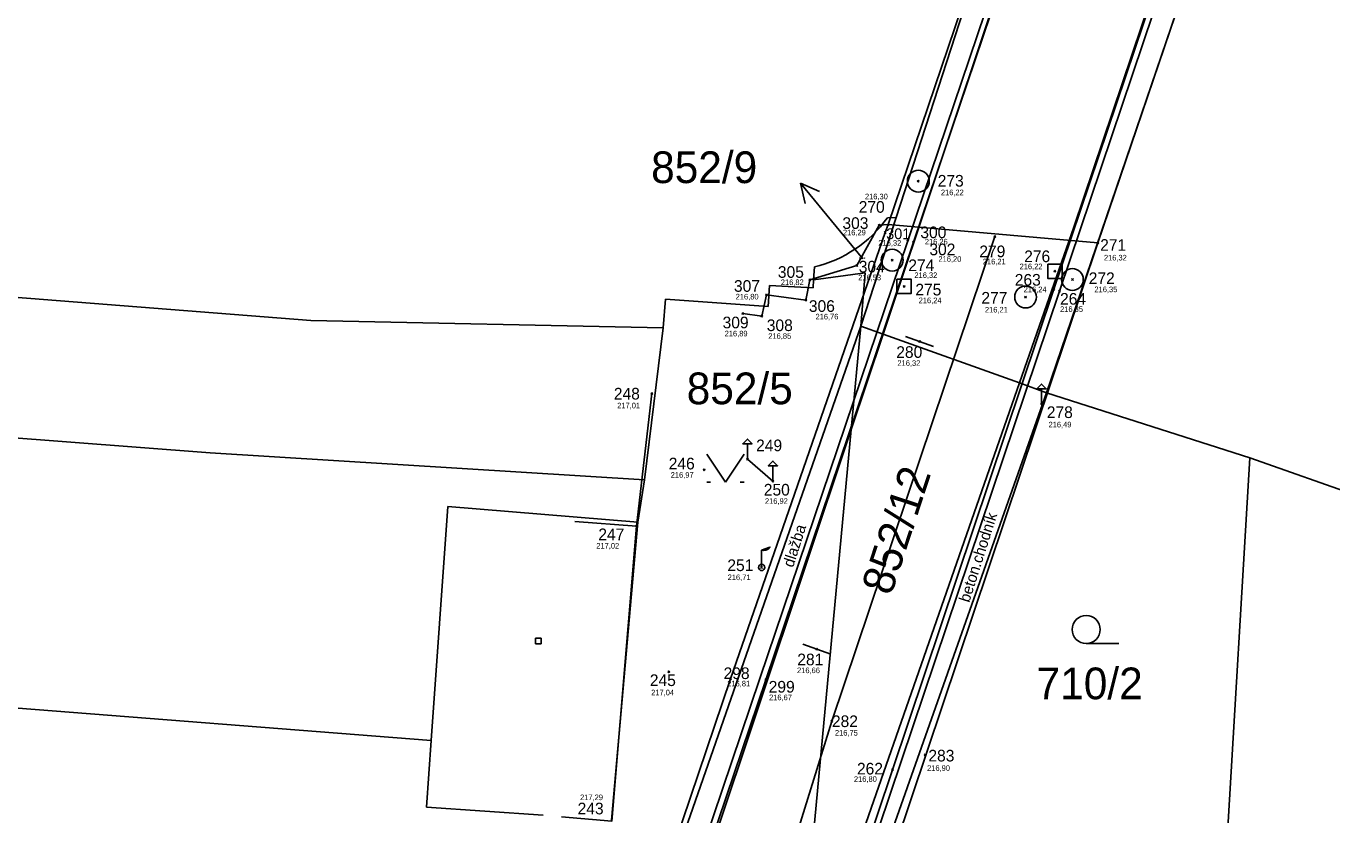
# Model space of a CAD drawing. Extents: x -711879 to -711361, y -1048782 to -1048177.
# Drawn here: x -711669.9 to -711599.9, y -1048480.8 to -1048438.5 of the extents above; entities that cross this region are included whole.
import ezdxf

# ---------------------------------------------------------------- set-up
doc = ezdxf.new("R2010")
doc.units = 0
for name, color, linetype in [('body', 7, 'Continuous'), ('kresba', 7, 'Continuous'), ('Vrstva 1', 7, 'Continuous'), ('Vrstva 13', 7, 'Continuous'), ('Vrstva 14', 7, 'Continuous'), ('Vrstva 16', 7, 'Continuous'), ('Vrstva 2', 7, 'Continuous'), ('Vrstva 20', 7, 'Continuous'), ('Vrstva 23', 7, 'Continuous'), ('Vrstva 25', 7, 'Continuous'), ('Vrstva 41', 7, 'Continuous'), ('Vrstva 46', 7, 'Continuous'), ('výšky', 7, 'Continuous')]:
    doc.layers.add(name, color=color, linetype=linetype)

msp = doc.modelspace()

# ---------------------------------------------------------------- linework, layer by layer
at = {"layer": 'kresba'}
for p, q in [((-711599.74, -1048407.86), (-711614.77, -1048452.56)), ((-711623.82, -1048449.52), (-711623.65, -1048449.1)), ((-711632.11, -1048473.45), (-711623.82, -1048449.52)), ((-711622.61, -1048449.96), (-711630.53, -1048473.44)), ((-711622.3, -1048450.03), (-711630.22, -1048473.51)), ((-711627.89, -1048496.13), (-711612.41, -1048450.08)), ((-711631.45, -1048453.87), (-711631.45, -1048453.87)), ((-711621.97, -1048455.37), (-711622.72, -1048455.1)), ((-711621.22, -1048455.64), (-711621.97, -1048455.37)), ((-711631.2, -1048461.67), (-711629.83, -1048462.85)), ((-711630.44, -1048466.55), (-711630.44, -1048467.48)), ((-711627.48, -1048471.87), (-711628.23, -1048471.6)), ((-711626.73, -1048472.14), (-711627.48, -1048471.87)), ((-711632.11, -1048473.45), (-711637.58, -1048489.62)), ((-711630.53, -1048473.44), (-711636.99, -1048492.57)), ((-711630.22, -1048473.51), (-711636.68, -1048492.64))]:
    msp.add_line(p, q, dxfattribs=at)
for points in [[(-711630.48, -1048500.11), (-711629, -1048495.83), (-711614.47, -1048452.67), (-711599.94, -1048409.51)], [(-711614.09, -1048419.16), (-711613.1, -1048421.84), (-711622.61, -1048449.96)], [(-711613.78, -1048419.23), (-711612.79, -1048421.91), (-711622.3, -1048450.03)], [(-711631.45, -1048453.87), (-711630.43, -1048454.01), (-711630.18, -1048452.87), (-711628.07, -1048453.14), (-711627.85, -1048452.06), (-711625.33, -1048451.29), (-711624.13, -1048449.12), (-711623.65, -1048449.1)], [(-711617.94, -1048449.74), (-711626.67, -1048475.73), (-711634.71, -1048501.65), (-711638.73, -1048513.57), (-711639.471, -1048515.651)], [(-711614.77, -1048452.56), (-711623.43, -1048478.33), (-711629.27, -1048495.74)], [(-711615.43, -1048458.72), (-711615.43, -1048457.9), (-711615.18, -1048457.9), (-711615.43, -1048457.65), (-711615.68, -1048457.9), (-711615.43, -1048457.9)], [(-711631.2, -1048461.67), (-711631.2, -1048460.85), (-711630.95, -1048460.85), (-711631.2, -1048460.6), (-711631.45, -1048460.85), (-711631.2, -1048460.85)], [(-711629.83, -1048462.85), (-711629.83, -1048462.03), (-711629.58, -1048462.03), (-711629.83, -1048461.78), (-711630.08, -1048462.03), (-711629.83, -1048462.03)]]:
    msp.add_lwpolyline(points, dxfattribs=at)
for points in [[(-711614.39, -1048421.71), (-711602.91, -1048422.1), (-711612.41, -1048450.08), (-711623.65, -1048449.1)], [(-711615.105, -1048451.22), (-711614.335, -1048451.22), (-711614.335, -1048451.98), (-711615.105, -1048451.98)], [(-711623.185, -1048452.03), (-711622.415, -1048452.03), (-711622.415, -1048452.79), (-711623.185, -1048452.79)], [(-711630.44, -1048466.55), (-711630.34, -1048466.58), (-711630.21, -1048466.56), (-711630.09, -1048466.5), (-711629.99, -1048466.39)]]:
    msp.add_lwpolyline(points, close=True, dxfattribs=at)
for centre, radius in [((-711622.04, -1048446.77), 0.585), ((-711623.44, -1048451), 0.585), ((-711613.78, -1048452.04), 0.585), ((-711616.29, -1048452.98), 0.585), ((-711630.44, -1048467.48), 0.17)]:
    msp.add_circle(centre, radius, dxfattribs=at)
at = {"layer": 'Vrstva 1'}
for p, q in [((-711614.35, -1048421.34), (-711623.23, -1048448.72)), ((-711602.89, -1048422.08), (-711615.16, -1048458.11)), ((-711733.69, -1048448.01), (-711654.61, -1048454.24)), ((-711623.23, -1048448.72), (-711625.12, -1048454.55)), ((-711623.7, -1048448.73), (-711623.23, -1048448.72)), ((-711627.65, -1048452.05), (-711627.61, -1048451.36)), ((-711627.67, -1048452.49), (-711627.65, -1048452.05)), ((-711624.88, -1048451.69), (-711627.65, -1048452.05)), ((-711625.12, -1048454.55), (-711624.88, -1048451.69)), ((-711630.08, -1048453.49), (-711630.01, -1048452.36)), ((-711630.01, -1048452.36), (-711627.67, -1048452.49)), ((-711635.71, -1048454.64), (-711635.59, -1048453.09)), ((-711635.59, -1048453.09), (-711630.08, -1048453.49)), ((-711654.61, -1048454.24), (-711635.71, -1048454.64)), ((-711625.12, -1048454.55), (-711639.88, -1048496.88)), ((-711636.72, -1048462.78), (-711635.71, -1048454.64)), ((-711625.64, -1048460.08), (-711625.12, -1048454.55)), ((-711623.93, -1048454.98), (-711625.12, -1048454.55)), ((-711616.62, -1048457.59), (-711623.93, -1048454.98)), ((-711615.16, -1048458.11), (-711616.62, -1048457.59)), ((-711624.32, -1048484.08), (-711615.16, -1048458.11)), ((-711615.16, -1048458.11), (-711604.27, -1048461.61)), ((-711660, -1048461.34), (-711677.08, -1048460.02)), ((-711627.81, -1048483.37), (-711625.64, -1048460.08)), ((-711636.72, -1048462.78), (-711660, -1048461.34)), ((-711604.27, -1048461.61), (-711605.79, -1048487.1)), ((-711585.96, -1048468.04), (-711604.27, -1048461.61)), ((-711637.08, -1048465.05), (-711636.72, -1048462.78)), ((-711637.08, -1048465.05), (-711638.48, -1048481.03)), ((-711648.15, -1048476.76), (-711678.42, -1048474.4)), ((-711648.15, -1048476.76), (-711648.41, -1048480.33)), ((-711648.41, -1048480.33), (-711642.14, -1048480.77))]:
    msp.add_line(p, q, dxfattribs=at)
msp.add_arc((-711629.131, -1048444.877), 6.66, 283.20668, 324.64557, dxfattribs=at)
at = {"layer": 'Vrstva 13'}
msp.add_line((-711625.02, -1048450.94), (-711626.45, -1048449.19), dxfattribs=at)
at = {"layer": 'Vrstva 16'}
for p, q in [((-711626.45, -1048449.19), (-711628.349, -1048446.868)), ((-711628.349, -1048446.868), (-711628.103, -1048447.958)), ((-711628.349, -1048446.868), (-711627.329, -1048447.325))]:
    msp.add_line(p, q, dxfattribs=at)
at = {"layer": 'Vrstva 2'}
for p, q in [((-711613.71, -1048449.23), (-711604.27, -1048421.22)), ((-711612.72, -1048421.45), (-711623.93, -1048454.98)), ((-711616.62, -1048457.59), (-711613.71, -1048449.23)), ((-711623.93, -1048454.98), (-711625.64, -1048460.08)), ((-711625.75, -1048483.79), (-711616.62, -1048457.59)), ((-711625.64, -1048460.08), (-711639.27, -1048500.86)), ((-711647.25, -1048464.22), (-711648.15, -1048476.76)), ((-711647.25, -1048464.22), (-711637.08, -1048465.05))]:
    msp.add_line(p, q, dxfattribs=at)
at = {"layer": 'Vrstva 20'}
for p, q in [((-711622.04, -1048446.77), (-711622.09, -1048446.72)), ((-711622.04, -1048446.77), (-711622.09, -1048446.82)), ((-711622.04, -1048446.77), (-711621.99, -1048446.72)), ((-711622.04, -1048446.77), (-711621.99, -1048446.82)), ((-711624.13, -1048449.12), (-711624.18, -1048449.07)), ((-711624.13, -1048449.12), (-711624.18, -1048449.17)), ((-711624.13, -1048449.12), (-711624.08, -1048449.07)), ((-711624.13, -1048449.12), (-711624.08, -1048449.17)), ((-711623.65, -1048449.1), (-711623.7, -1048449.05)), ((-711623.65, -1048449.1), (-711623.7, -1048449.15)), ((-711623.65, -1048449.1), (-711623.6, -1048449.05)), ((-711623.65, -1048449.1), (-711623.6, -1048449.15)), ((-711623.82, -1048449.52), (-711623.87, -1048449.47)), ((-711623.82, -1048449.52), (-711623.87, -1048449.57)), ((-711623.82, -1048449.52), (-711623.77, -1048449.47)), ((-711623.82, -1048449.52), (-711623.77, -1048449.57)), ((-711622.61, -1048449.96), (-711622.66, -1048449.91)), ((-711622.61, -1048449.96), (-711622.66, -1048450.01)), ((-711622.61, -1048449.96), (-711622.56, -1048449.91)), ((-711622.61, -1048449.96), (-711622.56, -1048450.01)), ((-711622.3, -1048450.03), (-711622.35, -1048449.98)), ((-711622.3, -1048450.03), (-711622.35, -1048450.08)), ((-711622.3, -1048450.03), (-711622.25, -1048449.98)), ((-711622.3, -1048450.03), (-711622.25, -1048450.08)), ((-711617.94, -1048449.74), (-711617.99, -1048449.69)), ((-711617.94, -1048449.74), (-711617.99, -1048449.79)), ((-711617.94, -1048449.74), (-711617.89, -1048449.69)), ((-711617.94, -1048449.74), (-711617.89, -1048449.79)), ((-711612.41, -1048450.08), (-711612.46, -1048450.03)), ((-711612.41, -1048450.08), (-711612.36, -1048450.03)), ((-711612.41, -1048450.08), (-711612.46, -1048450.13)), ((-711612.41, -1048450.08), (-711612.36, -1048450.13)), ((-711625.33, -1048451.29), (-711625.38, -1048451.24)), ((-711625.33, -1048451.29), (-711625.38, -1048451.34)), ((-711625.33, -1048451.29), (-711625.28, -1048451.24)), ((-711625.33, -1048451.29), (-711625.28, -1048451.34)), ((-711623.44, -1048451), (-711623.49, -1048450.95)), ((-711623.44, -1048451), (-711623.49, -1048451.05)), ((-711623.44, -1048451), (-711623.39, -1048450.95)), ((-711623.44, -1048451), (-711623.39, -1048451.05)), ((-711627.85, -1048452.06), (-711627.9, -1048452.01)), ((-711627.85, -1048452.06), (-711627.9, -1048452.11)), ((-711627.85, -1048452.06), (-711627.8, -1048452.01)), ((-711627.85, -1048452.06), (-711627.8, -1048452.11)), ((-711614.72, -1048451.6), (-711614.77, -1048451.55)), ((-711614.72, -1048451.6), (-711614.77, -1048451.65)), ((-711614.72, -1048451.6), (-711614.67, -1048451.55)), ((-711614.72, -1048451.6), (-711614.67, -1048451.65)), ((-711613.78, -1048452.04), (-711613.83, -1048451.99)), ((-711613.78, -1048452.04), (-711613.83, -1048452.09)), ((-711613.78, -1048452.04), (-711613.73, -1048451.99)), ((-711613.78, -1048452.04), (-711613.73, -1048452.09)), ((-711630.18, -1048452.87), (-711630.23, -1048452.82)), ((-711630.18, -1048452.87), (-711630.13, -1048452.82)), ((-711622.8, -1048452.41), (-711622.85, -1048452.36)), ((-711622.8, -1048452.41), (-711622.85, -1048452.46)), ((-711622.8, -1048452.41), (-711622.75, -1048452.36)), ((-711622.8, -1048452.41), (-711622.75, -1048452.46)), ((-711614.77, -1048452.56), (-711614.82, -1048452.51)), ((-711614.77, -1048452.56), (-711614.82, -1048452.61)), ((-711614.77, -1048452.56), (-711614.72, -1048452.51)), ((-711614.77, -1048452.56), (-711614.72, -1048452.61)), ((-711614.47, -1048452.67), (-711614.52, -1048452.62)), ((-711614.47, -1048452.67), (-711614.52, -1048452.72)), ((-711614.47, -1048452.67), (-711614.42, -1048452.62)), ((-711614.47, -1048452.67), (-711614.42, -1048452.72)), ((-711630.18, -1048452.87), (-711630.23, -1048452.92)), ((-711630.18, -1048452.87), (-711630.13, -1048452.92)), ((-711628.07, -1048453.14), (-711628.12, -1048453.09)), ((-711628.07, -1048453.14), (-711628.12, -1048453.19)), ((-711628.07, -1048453.14), (-711628.02, -1048453.09)), ((-711628.07, -1048453.14), (-711628.02, -1048453.19)), ((-711616.29, -1048452.98), (-711616.34, -1048452.93)), ((-711616.29, -1048452.98), (-711616.34, -1048453.03)), ((-711616.29, -1048452.98), (-711616.24, -1048452.93)), ((-711616.29, -1048452.98), (-711616.24, -1048453.03)), ((-711631.45, -1048453.87), (-711631.5, -1048453.82)), ((-711631.45, -1048453.87), (-711631.5, -1048453.92)), ((-711631.45, -1048453.87), (-711631.4, -1048453.82)), ((-711631.45, -1048453.87), (-711631.4, -1048453.92)), ((-711630.43, -1048454.01), (-711630.48, -1048453.96)), ((-711630.43, -1048454.01), (-711630.48, -1048454.06)), ((-711630.43, -1048454.01), (-711630.38, -1048453.96)), ((-711630.43, -1048454.01), (-711630.38, -1048454.06)), ((-711621.97, -1048455.37), (-711622.02, -1048455.32)), ((-711621.97, -1048455.37), (-711622.02, -1048455.42)), ((-711621.97, -1048455.37), (-711621.92, -1048455.32)), ((-711621.97, -1048455.37), (-711621.92, -1048455.42)), ((-711636.32, -1048458.16), (-711636.37, -1048458.11)), ((-711636.32, -1048458.16), (-711636.37, -1048458.21)), ((-711636.32, -1048458.16), (-711636.27, -1048458.11)), ((-711636.32, -1048458.16), (-711636.27, -1048458.21)), ((-711615.43, -1048458.72), (-711615.48, -1048458.67)), ((-711615.43, -1048458.72), (-711615.48, -1048458.77)), ((-711615.43, -1048458.72), (-711615.38, -1048458.67)), ((-711615.43, -1048458.72), (-711615.38, -1048458.77)), ((-711631.2, -1048461.67), (-711631.25, -1048461.62)), ((-711631.2, -1048461.67), (-711631.25, -1048461.72)), ((-711631.2, -1048461.67), (-711631.15, -1048461.62)), ((-711631.2, -1048461.67), (-711631.15, -1048461.72)), ((-711629.83, -1048461.78), (-711630.08, -1048462.03)), ((-711629.83, -1048461.78), (-711629.58, -1048462.03)), ((-711633.52, -1048462.24), (-711633.57, -1048462.19)), ((-711633.52, -1048462.24), (-711633.57, -1048462.29)), ((-711633.52, -1048462.24), (-711633.47, -1048462.19)), ((-711633.52, -1048462.24), (-711633.47, -1048462.29)), ((-711629.83, -1048462.03), (-711630.08, -1048462.03)), ((-711629.83, -1048462.03), (-711629.58, -1048462.03)), ((-711629.83, -1048462.85), (-711629.88, -1048462.8)), ((-711629.83, -1048462.85), (-711629.88, -1048462.9)), ((-711629.83, -1048462.85), (-711629.78, -1048462.8)), ((-711629.83, -1048462.85), (-711629.78, -1048462.9)), ((-711637.15, -1048465.26), (-711637.2, -1048465.21)), ((-711637.15, -1048465.26), (-711637.2, -1048465.31)), ((-711637.15, -1048465.26), (-711637.1, -1048465.21)), ((-711637.15, -1048465.26), (-711637.1, -1048465.31)), ((-711630.44, -1048467.48), (-711630.49, -1048467.43)), ((-711630.44, -1048467.48), (-711630.49, -1048467.53)), ((-711630.44, -1048467.48), (-711630.39, -1048467.43)), ((-711630.44, -1048467.48), (-711630.39, -1048467.53)), ((-711627.48, -1048471.87), (-711627.53, -1048471.82)), ((-711627.48, -1048471.87), (-711627.53, -1048471.92)), ((-711627.48, -1048471.87), (-711627.43, -1048471.82)), ((-711627.48, -1048471.87), (-711627.43, -1048471.92)), ((-711635.42, -1048473.08), (-711635.47, -1048473.03)), ((-711635.42, -1048473.08), (-711635.47, -1048473.13)), ((-711635.42, -1048473.08), (-711635.37, -1048473.03)), ((-711635.42, -1048473.08), (-711635.37, -1048473.13)), ((-711632.11, -1048473.45), (-711632.16, -1048473.4)), ((-711632.11, -1048473.45), (-711632.16, -1048473.5)), ((-711632.11, -1048473.45), (-711632.06, -1048473.4)), ((-711632.11, -1048473.45), (-711632.06, -1048473.5)), ((-711630.22, -1048473.51), (-711630.27, -1048473.46)), ((-711630.22, -1048473.51), (-711630.27, -1048473.56)), ((-711630.22, -1048473.51), (-711630.17, -1048473.46)), ((-711630.22, -1048473.51), (-711630.17, -1048473.56)), ((-711626.67, -1048475.73), (-711626.72, -1048475.68)), ((-711626.67, -1048475.73), (-711626.72, -1048475.78)), ((-711626.67, -1048475.73), (-711626.62, -1048475.68)), ((-711626.67, -1048475.73), (-711626.62, -1048475.78)), ((-711621.67, -1048477.53), (-711621.72, -1048477.48)), ((-711621.67, -1048477.53), (-711621.72, -1048477.58)), ((-711621.67, -1048477.53), (-711621.62, -1048477.48)), ((-711621.67, -1048477.53), (-711621.62, -1048477.58)), ((-711623.43, -1048478.33), (-711623.48, -1048478.28)), ((-711623.43, -1048478.33), (-711623.48, -1048478.38)), ((-711623.43, -1048478.33), (-711623.38, -1048478.28)), ((-711623.43, -1048478.33), (-711623.38, -1048478.38))]:
    msp.add_line(p, q, dxfattribs=at)
msp.add_lwpolyline([(-711629.83, -1048462.85), (-711629.83, -1048462.85), (-711629.83, -1048462.03)], dxfattribs=at)
at = {"layer": 'Vrstva 23'}
for p, q in [((-711633.38, -1048461.4), (-711632.38, -1048462.9)), ((-711632.38, -1048462.9), (-711631.38, -1048461.4)), ((-711633.38, -1048462.9), (-711633.18, -1048462.9)), ((-711631.58, -1048462.9), (-711631.38, -1048462.9)), ((-711613.04, -1048471.56), (-711611.29, -1048471.56))]:
    msp.add_line(p, q, dxfattribs=at)
msp.add_circle((-711613.04, -1048470.81), 0.75, dxfattribs=at)
at = {"layer": 'Vrstva 25'}
for p, q in [((-711642.56, -1048471.27), (-711642.26, -1048471.27)), ((-711642.56, -1048471.57), (-711642.56, -1048471.27)), ((-711642.26, -1048471.57), (-711642.56, -1048471.57)), ((-711642.26, -1048471.27), (-711642.26, -1048471.57))]:
    msp.add_line(p, q, dxfattribs=at)
at = {"layer": 'Vrstva 41'}
for p, q in [((-711622.04, -1048446.77), (-711622.04, -1048446.77)), ((-711624.13, -1048449.12), (-711624.13, -1048449.12)), ((-711623.65, -1048449.1), (-711623.65, -1048449.1)), ((-711623.82, -1048449.52), (-711623.82, -1048449.52)), ((-711622.61, -1048449.96), (-711622.61, -1048449.96)), ((-711622.3, -1048450.03), (-711622.3, -1048450.03)), ((-711617.94, -1048449.74), (-711617.94, -1048449.74)), ((-711612.41, -1048450.08), (-711612.41, -1048450.08)), ((-711625.33, -1048451.29), (-711625.33, -1048451.29)), ((-711623.44, -1048451), (-711623.44, -1048451)), ((-711627.85, -1048452.06), (-711627.85, -1048452.06)), ((-711614.72, -1048451.6), (-711614.72, -1048451.6)), ((-711613.78, -1048452.04), (-711613.78, -1048452.04)), ((-711622.8, -1048452.41), (-711622.8, -1048452.41)), ((-711614.77, -1048452.56), (-711614.77, -1048452.56)), ((-711614.47, -1048452.67), (-711614.47, -1048452.67)), ((-711630.18, -1048452.87), (-711630.18, -1048452.87)), ((-711628.07, -1048453.14), (-711628.07, -1048453.14)), ((-711616.29, -1048452.98), (-711616.29, -1048452.98)), ((-711631.45, -1048453.87), (-711631.45, -1048453.87)), ((-711630.43, -1048454.01), (-711630.43, -1048454.01)), ((-711621.97, -1048455.37), (-711621.97, -1048455.37)), ((-711636.32, -1048458.16), (-711636.32, -1048458.16)), ((-711615.43, -1048458.72), (-711615.43, -1048458.72)), ((-711631.2, -1048461.67), (-711631.2, -1048461.67)), ((-711633.52, -1048462.24), (-711633.52, -1048462.24)), ((-711629.83, -1048462.85), (-711629.83, -1048462.85)), ((-711629.83, -1048462.85), (-711629.83, -1048462.85)), ((-711637.15, -1048465.26), (-711637.15, -1048465.26)), ((-711630.44, -1048467.48), (-711630.44, -1048467.48)), ((-711627.48, -1048471.87), (-711627.48, -1048471.87)), ((-711635.42, -1048473.08), (-711635.42, -1048473.08)), ((-711632.11, -1048473.45), (-711632.11, -1048473.45)), ((-711630.22, -1048473.51), (-711630.22, -1048473.51)), ((-711626.67, -1048475.73), (-711626.67, -1048475.73)), ((-711621.67, -1048477.53), (-711621.67, -1048477.53)), ((-711623.43, -1048478.33), (-711623.43, -1048478.33))]:
    msp.add_line(p, q, dxfattribs=at)
at = {"layer": 'Vrstva 46'}
for p, q in [((-711637.15, -1048465.26), (-711636.32, -1048458.16)), ((-711660, -1048461.34), (-711660, -1048461.34)), ((-711647.25, -1048464.22), (-711647.25, -1048464.22)), ((-711637.15, -1048465.26), (-711640.45, -1048465.01)), ((-711648.41, -1048480.33), (-711648.41, -1048480.33))]:
    msp.add_line(p, q, dxfattribs=at)
msp.add_lwpolyline([(-711637.15, -1048465.26), (-711638.46, -1048481.08), (-711641.17, -1048480.856)], dxfattribs=at)

# ---------------------------------------------------------------- texts
at = {"layer": 'body'}
for s, height, p in [('273', 0.625, (-711621, -1048447.06)), ('270', 0.625, (-711625.236, -1048448.461)), ('303', 0.625, (-711626.108, -1048449.329)), ('301', 0.5782, (-711623.761, -1048449.878)), ('300', 0.625, (-711621.93, -1048449.824)), ('271', 0.625, (-711612.292, -1048450.503)), ('302', 0.625, (-711621.447, -1048450.74)), ('279', 0.625, (-711618.77, -1048450.845)), ('276', 0.625, (-711616.365, -1048451.11)), ('305', 0.625, (-711629.568, -1048451.951)), ('304', 0.6261, (-711625.232, -1048451.664)), ('274', 0.625, (-711622.577, -1048451.59)), ('307', 0.625, (-711631.922, -1048452.7)), ('263', 0.625, (-711616.87, -1048452.37)), ('272', 0.625, (-711612.906, -1048452.285)), ('275', 0.625, (-711622.199, -1048452.894)), ('277', 0.625, (-711618.66, -1048453.335)), ('264', 0.625, (-711614.444, -1048453.39)), ('306', 0.625, (-711627.906, -1048453.778)), ('309', 0.625, (-711632.531, -1048454.659)), ('308', 0.625, (-711630.162, -1048454.807)), ('280', 0.625, (-711623.222, -1048456.244)), ('248', 0.625, (-711638.36, -1048458.476)), ('278', 0.625, (-711615.153, -1048459.47)), ('249', 0.625, (-711630.734, -1048461.249)), ('246', 0.625, (-711635.419, -1048462.223)), ('250', 0.625, (-711630.322, -1048463.626)), ('247', 0.625, (-711639.192, -1048466.02)), ('251', 0.625, (-711632.276, -1048467.675)), ('281', 0.625, (-711628.527, -1048472.729)), ('298', 0.625, (-711632.477, -1048473.467)), ('245', 0.625, (-711636.431, -1048473.841)), ('299', 0.625, (-711630.059, -1048474.193)), ('282', 0.625, (-711626.67, -1048476.042)), ('283', 0.625, (-711621.5, -1048477.886)), ('262', 0.625, (-711625.329, -1048478.584)), ('243', 0.625, (-711640.302, -1048480.723))]:
    msp.add_text(s, height=height, dxfattribs=at).set_placement(p)
at = {"layer": 'kresba'}
for s, height, p in [('beton.chodník', 0.59303, (-711619.312, -1048469.397)), ('dlažba', 0.593, (-711628.752, -1048467.517))]:
    msp.add_text(s, height=height, rotation=72.35823, dxfattribs=at).set_placement(p)
at = {"layer": 'Vrstva 14'}
for s, height, p in [('852/9', 0.1, (-711625.226, -1048450.94)), ('852/5', 1.7, (-711634.455, -1048458.729)), ('710/2', 1.7, (-711615.7, -1048474.55))]:
    msp.add_text(s, height=height, dxfattribs=at).set_placement(p)
msp.add_text('852/12', height=1.7, rotation=71.90334, dxfattribs=at).set_placement((-711623.502, -1048469.041))
at = {"layer": 'Vrstva 16'}
msp.add_text('852/9', height=1.7, dxfattribs=at).set_placement((-711636.362, -1048446.87))
at = {"layer": 'výšky'}
for s, p in [('216,22', (-711620.83, -1048447.52)), ('216,30', (-711624.9, -1048447.74)), ('216,29', (-711626.08, -1048449.67)), ('216,32', (-711624.18, -1048450.23)), ('216,26', (-711621.69, -1048450.16)), ('216,32', (-711612.09, -1048451.02)), ('216,20', (-711620.96, -1048451.09)), ('216,21', (-711618.584, -1048451.229)), ('216,22', (-711616.61, -1048451.49)), ('216,82', (-711629.41, -1048452.34)), ('216,53', (-711625.26, -1048452.08)), ('216,32', (-711622.25, -1048451.96)), ('216,80', (-711631.83, -1048453.11)), ('216,24', (-711616.39, -1048452.72)), ('216,35', (-711612.6, -1048452.72)), ('216,24', (-711622.02, -1048453.31)), ('216,21', (-711618.47, -1048453.81)), ('216,35', (-711614.44, -1048453.78)), ('216,76', (-711627.55, -1048454.18)), ('216,89', (-711632.42, -1048455.09)), ('216,85', (-711630.08, -1048455.22)), ('216,32', (-711623.16, -1048456.67)), ('217,01', (-711638.18, -1048458.95)), ('216,49', (-711615.06, -1048459.97)), ('216,97', (-711635.31, -1048462.67)), ('216,92', (-711630.26, -1048464.07)), ('217,02', (-711639.3, -1048466.47)), ('216,71', (-711632.26, -1048468.16)), ('216,66', (-711628.54, -1048473.15)), ('216,81', (-711632.28, -1048473.86)), ('217,04', (-711636.36, -1048474.34)), ('216,67', (-711630.04, -1048474.6)), ('216,75', (-711626.51, -1048476.5)), ('216,80', (-711625.49, -1048478.98)), ('216,90', (-711621.57, -1048478.39)), ('217,29', (-711640.17, -1048479.96))]:
    msp.add_text(s, height=0.3, dxfattribs=at).set_placement(p)

doc.saveas('drawing.dxf')
